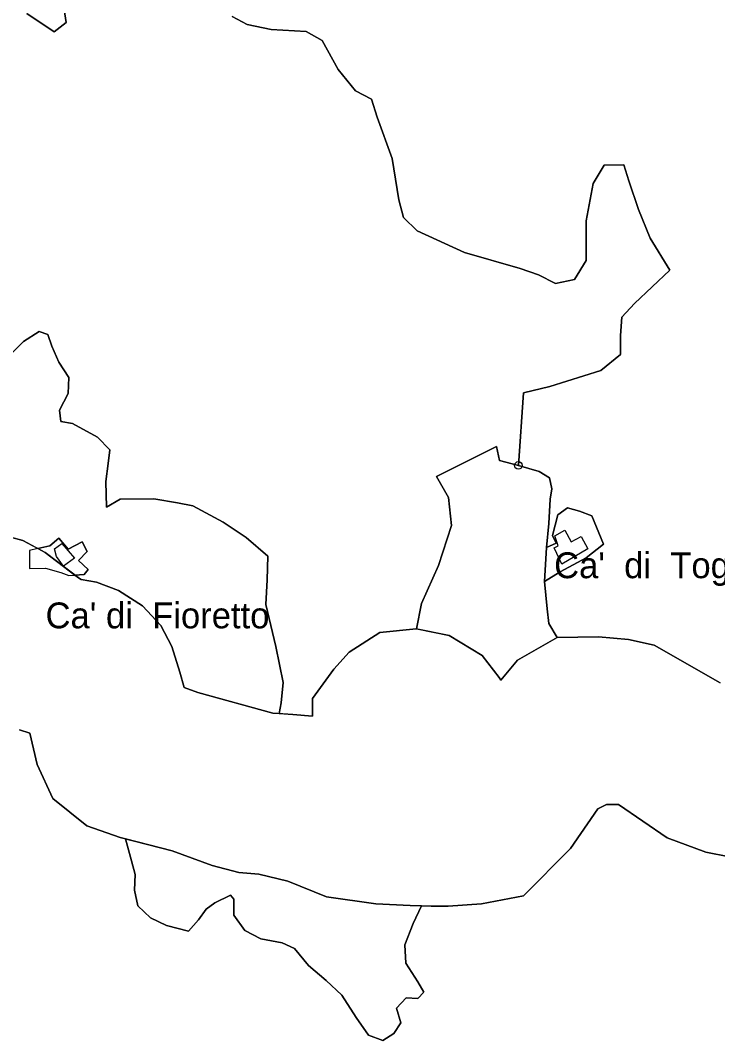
# Model space of a CAD drawing. Extents: x 645880 to 658994, y 884400 to 894744.
# Drawn here: x 653443 to 653901, y 891694 to 892365 of the extents above; entities that cross this region are included whole.
import ezdxf
from ezdxf.enums import TextEntityAlignment as Align

# ---------------------------------------------------------------- set-up
doc = ezdxf.new("R2010")
doc.units = 0
doc.header["$LTSCALE"] = 10
doc.header["$PDMODE"] = 32
doc.header["$PDSIZE"] = 5
for name, color, linetype, lineweight in [('16', 7, 'Continuous', 25), ('18', 7, 'Continuous', 25), ('2', 7, 'Continuous', 25), ('4', 7, 'Continuous', 25), ('55', 7, 'Continuous', 25)]:
    doc.layers.add(name, color=color, linetype=linetype, lineweight=lineweight)
doc.layers.add('60', color=7, linetype='Continuous')

msp = doc.modelspace()

# ---------------------------------------------------------------- linework, layer by layer
at = {"layer": '16'}
for points in [[(653447.25, 892369.86), (653465.3, 892357.81), (653473.24, 892363.94), (653470.61, 892381.05)], [(653582.27, 892367.91), (653592.12, 892362.65), (653607.9, 892359.36), (653630.9, 892358.04), (653641.41, 892352.12), (653651.93, 892333.04), (653663.27, 892318.99), (653673.75, 892313.64), (653677.63, 892301.76), (653687.35, 892274.52), (653691.67, 892247.29)], [(653691.67, 892247.29), (653694.91, 892235.76), (653703.85, 892227.09), (653734.87, 892212.72), (653771.58, 892202.24), (653783.46, 892198.05), (653794.79, 892192.3), (653807.22, 892194.91), (653814.78, 892207.48), (653814.78, 892233.67), (653819.54, 892258.11), (653826.67, 892270.15), (653839.61, 892270.33), (653842.85, 892259.86), (653849.33, 892241), (653856.89, 892222.14), (653869.85, 892201.19), (653846.73, 892179.14), (653838.26, 892170.21), (653837.46, 892158.24), (653837.46, 892145.67), (653824.5, 892135.19), (653791.02, 892124.72), (653773.74, 892120.53), (653770.37, 892072.72)], [(653478.89, 892000.65), (653481.89, 891998.36), (653483.08, 891997.7), (653493.02, 891996.04), (653507.54, 891990.37), (653523.21, 891980.49), (653535.35, 891967.48), (653542.65, 891953.68), (653547.94, 891936.81), (653550.75, 891926.57), (653559.65, 891923.44), (653608.88, 891909.77), (653613.09, 891909.5), (653614.41, 891916.49), (653615.71, 891930.03), (653610.85, 891953.6), (653604.37, 891981.36), (653605.3, 891997.5), (653605.7, 892013.15), (653591.44, 892025.23), (653576.29, 892035.32), (653556.41, 892046.23), (653546.27, 892048.04), (653530.68, 892050.78), (653508.71, 892050.59), (653499.6, 892045.24), (653499.21, 892062.07), (653500.69, 892074.08), (653501.78, 892083.07), (653493.67, 892091.37), (653477.24, 892100.31), (653469.74, 892101.67), (653468.75, 892108.99), (653474.41, 892120.03), (653474.95, 892130.51), (653468.33, 892140.7), (653463.78, 892151.21), (653461.21, 892158.74), (653455.47, 892160.72), (653445.17, 892154.18)], [(653445.17, 892154.18), (653426.17, 892135.37), (653418.25, 892125.79), (653412.31, 892120.03), (653402.53, 892117.01)], [(653770.37, 892072.72), (653757.88, 892076.01), (653755.91, 892085.22), (653716.48, 892065.48), (653724.37, 892051.66), (653726.34, 892033.24), (653717.8, 892006.92), (653706.62, 891981.91), (653703.36, 891965.16), (653724.73, 891960.89)], [(653770.37, 892072.72), (653784.06, 892068.69), (653790.79, 892064.54), (653792.35, 892057.29), (653791.31, 892050.55), (653790.27, 892034.49), (653788.81, 892018.7)], [(653788.81, 892018.7), (653790.27, 892034.49), (653791.31, 892050.55), (653792.35, 892057.29), (653790.79, 892064.54), (653784.06, 892068.69), (653770.37, 892072.72)], [(653788.81, 892018.7), (653795.08, 892021.61), (653792.77, 892026.68), (653796.23, 892040.3), (653802.69, 892044.92), (653810.53, 892042.61), (653818.6, 892039.61), (653826.21, 892020.91), (653814.91, 892011.91), (653797.84, 892002.68), (653787.43, 891996.36), (653789.24, 891978.52)], [(653428.32, 892027.66), (653444.68, 892023.45), (653454.58, 892018.12), (653462.37, 892019.88), (653468.25, 892024.84), (653474.37, 892017.68), (653483.59, 892022.53), (653486.94, 892016.18), (653481.17, 892010.18), (653487.51, 892004.3), (653484.98, 892001.07), (653478.89, 892000.65)], [(653795.71, 891959.47), (653790.27, 891968.67), (653789.24, 891978.52), (653787.43, 891996.36), (653788.74, 892018.7)], [(653789.24, 891978.52), (653790.27, 891968.67), (653795.71, 891959.47)], [(653724.73, 891960.89), (653746.57, 891947.62), (653757.69, 891933.22), (653758.82, 891931.41), (653769.72, 891944.73), (653795.71, 891959.47)], [(653795.71, 891959.47), (653823.03, 891959.98), (653842.64, 891958.35), (653859.53, 891954.59), (653902.84, 891929.76)], [(653706.63, 891783.04), (653699.3, 891783.35), (653676.6, 891784.48), (653644.25, 891789.02), (653618.72, 891799.25), (653599.77, 891804), (653586.63, 891804.97), (653569.03, 891809.63), (653542.86, 891819.2), (653512.09, 891827.19), (653515.98, 891812.76), (653518.43, 891803.59), (653518.02, 891793.41), (653520.26, 891783.03), (653528.6, 891775.29), (653539.18, 891770.2), (653553.63, 891766.33), (653560.06, 891773.95), (653565.23, 891780.79), (653570.95, 891785.02), (653581.1, 891790.15), (653583.4, 891787.53), (653583.4, 891776.97), (653590.66, 891766.91), (653601.03, 891761.37), (653615.03, 891758.86), (653623.17, 891754.98), (653632.5, 891743.91), (653643.97, 891733.97), (653654.28, 891724.29)], [(653654.28, 891724.29), (653663.62, 891709.7), (653671.92, 891698.13), (653681.21, 891694.46), (653688.54, 891699.14), (653693.02, 891706.07), (653690.16, 891715.84), (653696.47, 891722.56), (653704.25, 891722.09), (653708.16, 891726.36), (653704.21, 891733.15), (653696.27, 891745.37), (653695.77, 891757.5), (653701.15, 891771.43), (653706.63, 891783.04)]]:
    msp.add_lwpolyline(points, dxfattribs=at)
msp.add_point((653770.37, 892072.72), dxfattribs=at)
at = {"layer": '18'}
for points in [[(653470.61, 892381.05), (653473.24, 892363.94), (653465.3, 892357.81), (653447.25, 892369.86)], [(653694.91, 892235.76), (653691.67, 892247.29), (653687.35, 892274.52), (653677.63, 892301.76), (653673.75, 892313.64), (653663.27, 892318.99), (653651.93, 892333.04), (653641.41, 892352.12), (653630.9, 892358.04), (653607.9, 892359.36), (653592.12, 892362.65), (653582.27, 892367.91)], [(653613.09, 891909.5), (653622.15, 891908.91), (653635.09, 891907.74), (653635.09, 891919.48), (653648.99, 891938.74), (653659.02, 891950.02), (653679.3, 891962.85), (653703.06, 891965.22), (653703.36, 891965.16), (653706.62, 891981.91), (653717.8, 892006.92), (653726.34, 892033.24), (653724.37, 892051.66), (653716.48, 892065.48), (653755.91, 892085.22), (653757.88, 892076.01), (653770.37, 892072.72), (653773.74, 892120.53), (653791.02, 892124.72), (653824.5, 892135.19), (653837.46, 892145.67), (653837.46, 892158.24), (653838.26, 892170.21), (653846.73, 892179.14), (653869.85, 892201.19), (653856.89, 892222.14), (653849.33, 892241), (653842.85, 892259.86), (653839.61, 892270.33), (653826.67, 892270.15), (653819.54, 892258.11), (653814.78, 892233.67), (653814.78, 892207.48), (653807.22, 892194.91), (653794.79, 892192.3), (653783.46, 892198.05), (653771.58, 892202.24), (653734.87, 892212.72), (653703.85, 892227.09), (653694.91, 892235.76)], [(653426.17, 892135.37), (653445.17, 892154.18), (653455.47, 892160.72), (653461.21, 892158.74), (653463.78, 892151.21), (653468.33, 892140.7), (653474.95, 892130.51), (653474.41, 892120.03), (653468.75, 892108.99), (653469.74, 892101.67), (653477.24, 892100.31), (653493.67, 892091.37), (653501.78, 892083.07), (653500.69, 892074.08), (653499.21, 892062.07), (653499.6, 892045.24), (653508.71, 892050.59), (653530.68, 892050.78), (653546.27, 892048.04), (653556.41, 892046.23), (653576.29, 892035.32), (653591.44, 892025.23), (653605.7, 892013.15), (653605.3, 891997.5), (653604.37, 891981.36), (653610.85, 891953.6), (653615.71, 891930.03), (653614.41, 891916.49), (653613.09, 891909.5)], [(653486.68, 891835.79), (653464.3, 891853.71), (653454.16, 891876.01), (653449.23, 891896.62), (653442.41, 891898.73)], [(653909.09, 891815.3), (653893.52, 891818.42), (653868, 891827.83), (653836.07, 891849.78), (653828.33, 891849.8), (653822.45, 891846.94), (653804.61, 891820.85), (653773.64, 891789.59), (653746.05, 891784.44), (653724.27, 891782.85), (653712.92, 891782.78), (653706.63, 891783.04), (653701.15, 891771.43), (653695.77, 891757.5), (653696.27, 891745.37), (653704.21, 891733.15), (653708.16, 891726.36), (653704.25, 891722.09), (653696.47, 891722.56), (653690.16, 891715.84), (653693.02, 891706.07), (653688.54, 891699.14), (653681.21, 891694.46), (653671.92, 891698.13), (653663.62, 891709.7), (653654.28, 891724.29), (653643.97, 891733.97), (653632.5, 891743.91), (653623.17, 891754.98), (653615.03, 891758.86), (653601.03, 891761.37), (653590.66, 891766.91), (653583.4, 891776.97), (653583.4, 891787.53), (653581.1, 891790.15), (653570.95, 891785.02), (653565.23, 891780.79), (653560.06, 891773.95), (653553.63, 891766.33)], [(653512.09, 891827.19), (653508.56, 891828.1), (653486.68, 891835.79)], [(653553.63, 891766.33), (653539.18, 891770.2), (653528.6, 891775.29), (653520.26, 891783.03), (653518.02, 891793.41), (653518.43, 891803.59), (653515.98, 891812.76), (653512.09, 891827.19)]]:
    msp.add_lwpolyline(points, dxfattribs=at)
at = {"layer": '2'}
msp.add_lwpolyline([(653454.58, 892018.12), (653459.44, 892015.5), (653478.89, 892000.65), (653484.98, 892001.07), (653487.51, 892004.3), (653481.17, 892010.18), (653486.94, 892016.18), (653483.59, 892022.53), (653474.37, 892017.68), (653468.25, 892024.84), (653462.37, 892019.88)], close=True, dxfattribs=at)
for points in [[(653478.89, 892000.65), (653459.44, 892015.5), (653454.58, 892018.12), (653449.11, 892016.88), (653449, 892005)], [(653449, 892005), (653459.61, 892005.23), (653469.76, 892002.23), (653474.83, 892000.38), (653478.89, 892000.65)]]:
    msp.add_lwpolyline(points, dxfattribs=at)
at = {"layer": '4'}
msp.add_line((653795.08, 892021.61), (653788.81, 892018.7), dxfattribs=at)
msp.add_lwpolyline([(653788.74, 892018.73), (653787.43, 891996.36), (653797.84, 892002.68), (653814.91, 892011.91), (653826.21, 892020.91), (653818.6, 892039.61), (653810.53, 892042.61), (653802.69, 892044.92), (653796.23, 892040.3), (653792.77, 892026.68), (653795.08, 892021.61)], dxfattribs=at)
for points in [[(653794.22, 892026.46), (653800.83, 892030.09), (653805.04, 892022.44), (653811.58, 892026.03), (653816.02, 892017.94), (653798.89, 892007.77), (653793.76, 892018.61), (653796.56, 892019.93)], [(653465.41, 892017.9), (653470.3, 892021.36), (653478.64, 892011.79), (653471.38, 892006.5), (653466.74, 892012.86)]]:
    msp.add_lwpolyline(points, close=True, dxfattribs=at)
at = {"layer": '55'}
for points in [[(653902.84, 891929.76), (653859.53, 891954.59), (653842.64, 891958.35), (653823.03, 891959.98), (653795.71, 891959.47), (653769.72, 891944.73), (653758.82, 891931.41), (653757.69, 891933.22), (653746.57, 891947.62), (653724.73, 891960.89), (653703.06, 891965.22), (653679.3, 891962.85), (653659.02, 891950.02), (653648.99, 891938.74), (653635.09, 891919.48), (653635.09, 891907.74), (653622.15, 891908.91), (653608.88, 891909.77), (653559.65, 891923.44), (653550.75, 891926.57), (653547.94, 891936.81), (653542.65, 891953.68), (653535.35, 891967.48), (653523.21, 891980.49), (653507.54, 891990.37), (653493.02, 891996.04), (653483.08, 891997.7), (653481.89, 891998.36), (653459.44, 892015.5), (653444.68, 892023.45), (653428.32, 892027.66)], [(653442.41, 891898.73), (653449.23, 891896.62), (653454.16, 891876.01), (653464.3, 891853.71), (653486.68, 891835.79), (653508.56, 891828.1), (653542.86, 891819.2), (653569.03, 891809.63), (653586.63, 891804.97), (653599.77, 891804), (653618.72, 891799.25), (653644.25, 891789.02), (653676.6, 891784.48), (653699.3, 891783.35), (653712.92, 891782.78)], [(653712.92, 891782.78), (653724.27, 891782.85), (653746.05, 891784.44), (653773.64, 891789.59), (653804.61, 891820.85), (653822.45, 891846.94), (653828.33, 891849.8), (653836.07, 891849.78), (653868, 891827.83), (653893.52, 891818.42), (653909.09, 891815.3)]]:
    msp.add_lwpolyline(points, dxfattribs=at)

# ---------------------------------------------------------------- texts
at = {"layer": '60'}
for s, p in [("Ca'  di  Tognetto", (653876.83, 891998.56)), ("Ca' di  Fioretto", (653533.16, 891965.59))]:
    msp.add_text(s, height=17, dxfattribs=at).set_placement(p, align=Align.CENTER)

doc.saveas('drawing.dxf')
